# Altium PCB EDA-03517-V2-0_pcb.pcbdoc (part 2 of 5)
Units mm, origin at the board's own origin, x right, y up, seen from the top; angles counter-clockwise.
Board outline 220 x 264 mm, 8 copper layers (Top Layer, L2, L3, L4, L5, L6, L7, Bottom Layer), stack 2.18 mm thick; 439 components, 290 nets, 1011 pads, 273 vias.
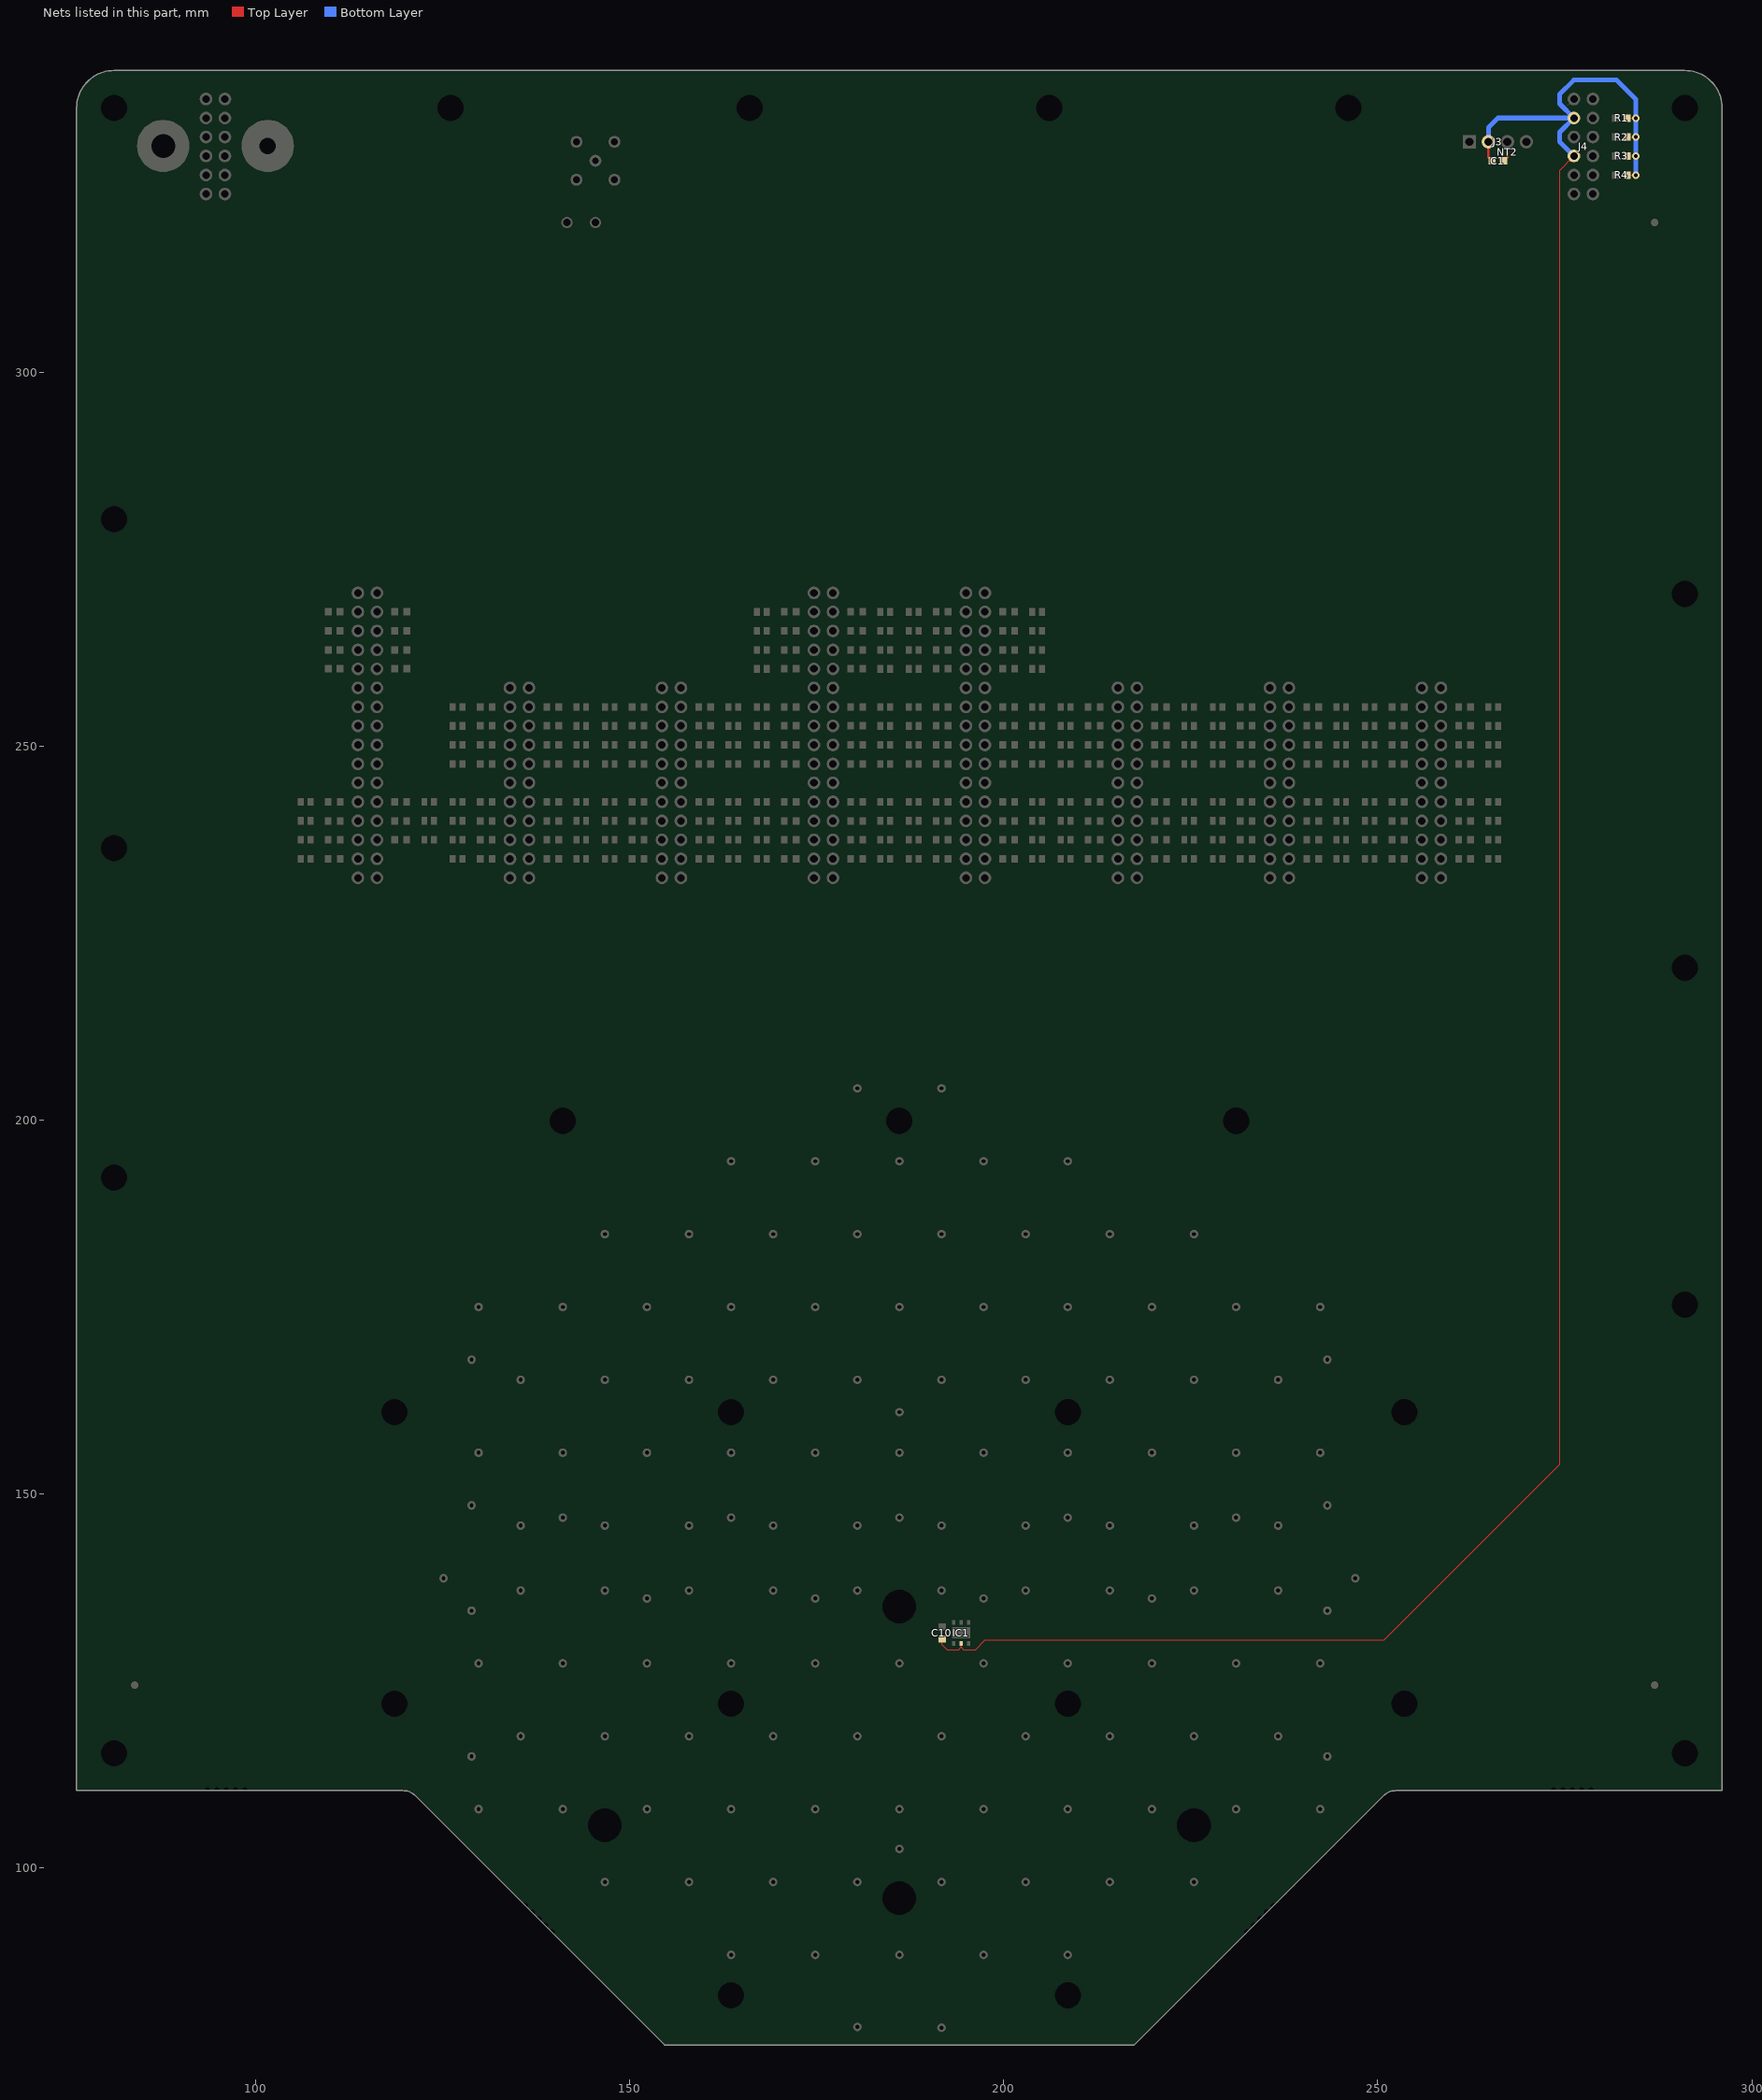
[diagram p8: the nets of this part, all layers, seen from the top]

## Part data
B1 B2: library part PLATED_HOLE1.0_PAD1.5, "Single Terminal Socket"
C1 C10: library part CC0603_100NF_50V_10%_X7R, "Non-polarised capacitor", Case=0603, Manufacturer=GENERIC, Manufacturer1 ComponentHeight=0.87mm, Manufacturer1 Example=PHYCOMP, Manufacturer1 Part Number=223858615649, Tolerance=±10%, Voltage=50V
C2: library part CC0603_1PF_50V_0.25PF_NP0, "Non-polarised capacitor", Case=0603, Manufacturer=GENERIC, Manufacturer1 ComponentHeight=0.87mm, Manufacturer1 Example=PHYCOMP, Manufacturer1 Part Number=223886715108, Tolerance=±0.25pF, Voltage=50V
C3: library part CC0603_2.2PF_50V_0.25PF_NP0, "Non-polarised capacitor", Case=0603, Manufacturer=GENERIC, Manufacturer1 ComponentHeight=0.87mm, Manufacturer1 Example=PHYCOMP, Manufacturer1 Part Number=223886715228, Tolerance=±0.25pF, Voltage=50V
C4: library part CC0603_4.7PF_50V_0.25PF_NP0, "Non-polarised capacitor", Case=0603, Manufacturer=GENERIC, Manufacturer1 ComponentHeight=0.87mm, Manufacturer1 Example=PHYCOMP, Manufacturer1 Part Number=223886715478, Tolerance=±0.25pF, Voltage=50V
C5: library part CC0603_10PF_50V_5%_NP0, "Non-polarised capacitor", Case=0603, Manufacturer=GENERIC, Manufacturer1 ComponentHeight=0.87mm, Manufacturer1 Example=PHYCOMP, Manufacturer1 Part Number=223886715109, Tolerance=±5%, Voltage=50V
C6: library part CC0603_22PF_50V_5%_NP0, "Non-polarised capacitor", Case=0603, Manufacturer=GENERIC, Manufacturer1 ComponentHeight=0.87mm, Manufacturer1 Example=PHYCOMP, Manufacturer1 Part Number=223886715229, Tolerance=±5%, Voltage=50V
C7: library part CC0603_47PF_50V_5%_NP0, "Non-polarised capacitor", Case=0603, Manufacturer=GENERIC, Manufacturer1 ComponentHeight=0.87mm, Manufacturer1 Example=PHYCOMP, Manufacturer1 Part Number=223886715479, Tolerance=±5%, Voltage=50V
C8: library part CC0603_100PF_50V_5%_NP0, "Non-polarised capacitor", Case=0603, Manufacturer=GENERIC, Manufacturer1 ComponentHeight=0.87mm, Manufacturer1 Example=PHYCOMP, Manufacturer1 Part Number=223886715101, Tolerance=±5%, Voltage=50V
C9: library part CC0603_220PF_50V_5%_NP0, "Non-polarised capacitor", Case=0603, Manufacturer=GENERIC, Manufacturer1 ComponentHeight=0.87mm, Manufacturer1 Example=PHYCOMP, Manufacturer1 Part Number=223886715221, Tolerance=±5%, Voltage=50V
FTG1 FTG2 FTG3: library part FIDUCIAL_TARGET_C100-200, "Fiducial Target"
IC1: "Humidity and Temperature Sensor IC", Case=SON6, Manufacturer=SENSIRION
J1 J4: library part SAMTEC_MTLW-106-07-L-D-250, "Connector 12 Male", Manufacturer=SAMTEC, Manufacturer Part Number=MTLW-106-07-L-D-250
J2: library part LEMO_EPK.00.250.NTN, Manufacturer=LEMO, Manufacturer Part Number=EPK.00.250.NTN
J3: library part SAMTEC_SSW-104-02-L-S-RA, "Connector 4 Female", Manufacturer=SAMTEC, Manufacturer Part Number=SSW-104-02-L-S-RA
J5 J8 J9: library part SAMTEC_MTLW-116-07-L-D-250, "Connector 32 Male", Manufacturer=SAMTEC, Manufacturer Part Number=MTLW-116-07-L-D-250
J6 J7 J10 J11 J12: library part SAMTEC_MTLW-111-07-L-D-250, "Connector 20 Male", Manufacturer=SAMTEC, Manufacturer Part Number=MTLW-111-07-L-D-250
PP1 PP2 PP3 PP4 PP5 PP6 PP7 PP8 PP9 PP10 PP11 PP12 PP13 PP14 PP15 PP16 PP17 PP18 PP19 PP20 PP21 PP22 PP23 PP24 PP25 PP26 PP27 PP28 PP29 PP30 PP31 PP32 PP33 PP34 PP35 PP36 PP37 PP38 PP39 PP40 PP41 PP42 PP43 PP44 PP45 PP46 PP47 PP48 PP49 PP50 PP51 PP52 PP53 PP54 PP55 PP56 PP57 PP58 PP59 PP60 PP61 PP62 PP63 PP64 PP65 PP66 PP67 PP68 PP69 PP70 PP71 PP72 PP73 PP74 PP75 PP76 PP77 PP78 PP79 PP80 PP81 PP82 PP83 PP84 PP85 PP86 PP87 PP88 PP89 PP90 PP91 PP92 PP93 PP94 PP95 PP96 PP97 PP98 PP99 PP100 PP101 PP102 PP103 PP104 PP105 PP106 PP107 PP108 PP109 PP110 PP111 PP112 PP113 PP114 PP115 PP116 PP117 PP118 PP119 PP120 PP121 PP122 PP123 PP124 PP125 PP126 PP127 PP128 PP129 PP130 PP131 PP132 PP133 PP134 PP135: library part MILL-MAX_0985-1-15-20-71-14-11-0, "Test Point", Manufacturer=MILL-MAX, Manufacturer Part Number=0985-1-15-20-71-14-11-0
R1 R2 R3 R4: library part R0603_10K_1%_0.1W_100PPM, "Resistor - 1%", Case=0603, Manufacturer=GENERIC, Manufacturer1 ComponentHeight=0.55mm, Manufacturer1 Example="NIC COMPONENT", Manufacturer1 Part Number=NRC06F1002TRF, Power=0.1W, Tolerance=±1%
RB1 RB2 RB3 RB4 RB5 RB6 RB7 RB8 RB9 RB10 RB11 RB12 RB13 RB14 RB15 RB16 RB17 RB18 RB19 RB20 RB21 RB22 RB23 RB24 RB25 RB26 RB27 RB28 RB29 RB30 RB31 RB32 RB33 RB34 RB35 RB36 RB37 RB38 RB39 RB40 RB41 RB42 RB43 RB44 RB45 RB46 RB47 RB48 RB49 RB50 RB51 RB52 RB53 RB54 RB55 RB56 RB57 RB58 RB59 RB60 RB61 RB62 RB63 RB64 RB65 RB66 RB67 RB68 RB69 RB70 RB71 RB72 RB73 RB74 RB75 RB76 RB77 RB78 RB79 RB80 RB81 RB82 RB83 RB84 RB85 RB86 RB87 RB88 RB89 RB90 RB91 RB92 RB93 RB94 RB95 RB96 RB97 RB98 RB99 RB100 RB101 RB102 RB103 RB104 RB105 RB106 RB107 RB108 RB109 RB110 RB111 RB112 RB113 RB114 RB115 RB116 RB117 RB118 RB119 RB120 RB121 RB122 RB123 RB124 RB125 RB126 RB127 RB128 RB129 RB130 RB131 RB132 RB133 RB134 RB135: library part R0603_10M_1%_0.125W_100PPM_VISHAY_CHP, "Resistor - 1%", Case=0603, Manufacturer="VISHAY SFERNICE", Manufacturer Part Number=CHP0603K1005FNT, Power=0.125W, Tolerance=±1%
RS1 RS2 RS3 RS4 RS5 RS6 RS7 RS8 RS9 RS10 RS11 RS12 RS13 RS14 RS15 RS16 RS17 RS18 RS19 RS20 RS21 RS22 RS23 RS24 RS25 RS26 RS27 RS28 RS29 RS30 RS31 RS32 RS33 RS34 RS35 RS36 RS37 RS38 RS39 RS40 RS41 RS42 RS43 RS44 RS45 RS46 RS47 RS48 RS49 RS50 RS51 RS52 RS53 RS54 RS55 RS56 RS57 RS58 RS59 RS60 RS61 RS62 RS63 RS64 RS65 RS66 RS67 RS68 RS69 RS70 RS71 RS72 RS73 RS74 RS75 RS76 RS77 RS78 RS79 RS80 RS81 RS82 RS83 RS84 RS85 RS86 RS87 RS88 RS89 RS90 RS91 RS92 RS93 RS94 RS95 RS96 RS97 RS98 RS99 RS100 RS101 RS102 RS103 RS104 RS105 RS106 RS107 RS108 RS109 RS110 RS111 RS112 RS113 RS114 RS115 RS116 RS117 RS118 RS119 RS120 RS121 RS122 RS123 RS124 RS125 RS126 RS127 RS128 RS129 RS130 RS131 RS132 RS133 RS134 RS135: library part R0603_0R_JUMPER, "Resistor", Case=0603, Manufacturer=GENERIC, Manufacturer1 ComponentHeight=0.55mm, Manufacturer1 Example="NIC COMPONENT", Manufacturer1 Part Number=NRC06Z0

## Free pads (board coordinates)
  round 1 hole 3.5 unplated mask+1.25: D350NP(81.055,115.36) D350NP(81.055,192.36) D350NP(81.055,236.36) D350NP(81.055,280.36) D350NP(81.055,335.36) D350NP(118.543,121.967) D350NP(118.543,160.945) D350NP(126.055,335.36) D350NP(141.047,199.923) D350NP(163.551,82.989) D350NP(163.551,121.967) D350NP(163.551,160.945) D350NP(166.055,335.36) D350NP(186.055,199.923) D350NP(206.055,335.36) D350NP(208.559,82.989) D350NP(208.559,121.967) D350NP(208.559,160.945) D350NP(231.063,199.923) D350NP(246.055,335.36) D350NP(253.567,121.967) D350NP(253.567,160.945) D350NP(291.055,115.36) D350NP(291.055,175.36) D350NP(291.055,220.36) D350NP(291.055,270.36) D350NP(291.055,335.36)
  round 7 hole 2.2: P28(101.6,330.282)
  round 7 hole 3.2: P29(87.63,330.282)
  round 0.5 hole 0.8 unplated mask+0.15: P80NP(93.555,110.36) P80NP(94.805,110.36) P80NP(96.055,110.36) P80NP(97.305,110.36) P80NP(98.555,110.36) P80NP(136.039,94.976) P80NP(136.923,94.092) P80NP(137.806,93.209) P80NP(138.69,92.325) P80NP(139.574,91.441) P80NP(232.544,91.449) P80NP(233.428,92.333) P80NP(234.312,93.217) P80NP(235.196,94.101) P80NP(236.08,94.985) P80NP(273.555,110.36) P80NP(274.805,110.36) P80NP(276.055,110.36) P80NP(277.305,110.36) P80NP(278.555,110.36)
  round 1 hole 4.5 unplated mask+1.75: P450NP(146.673,105.726) P450NP(186.055,95.982) P450NP(186.055,134.96) P450NP(225.425,105.726)

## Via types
v1: diameter 1, hole 0.5, Top Layer to Bottom Layer, tented both sides, 273 vias

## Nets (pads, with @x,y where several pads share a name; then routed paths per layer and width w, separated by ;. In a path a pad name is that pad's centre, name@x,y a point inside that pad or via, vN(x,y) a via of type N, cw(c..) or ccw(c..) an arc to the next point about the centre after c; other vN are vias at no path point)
3.3V: C1.2 C10.2 IC1.5 J3.2 J4.6 J4.10 R1.2 R2.2 R3.2 R4.2 | length 324.2
  Top Layer w0.152: C10.2@191.77,130.645 191.77,129.857 192.405,129.222 193.992,129.222 194.31,129.54 ; IC1.5@194.31,130.045 194.31,129.54 ; J4.6@276.225,328.93 274.32,327.025 274.32,153.987 250.825,130.493 197.485,130.493 196.215,129.222 194.627,129.222 194.31,129.54 ; R4.2@283.375,326.39 v1(284.48,326.39) ; R3.2@283.375,328.93 v1(284.48,328.93) ; R2.2@283.375,331.47 v1(284.48,331.47) ; R1.2@283.375,334.01 v1(284.48,334.01)
  Top Layer w0.305: J3.2@264.795,330.835 264.795,328.765 C1.2@265.265,328.295
  Bottom Layer w0.635: J3.2@264.795,330.835 264.795,332.74 266.065,334.01 J4.10@276.225,334.01 ; J4.6@276.225,328.93 274.32,330.835 274.32,332.105 J4.10@276.225,334.01 ; v1(284.48,326.39) v1(284.48,328.93) v1(284.48,331.47) v1(284.48,334.01) 284.48,336.55 281.94,339.09 276.225,339.09 274.32,337.185 274.32,335.915 J4.10@276.225,334.01
CGND: C1.1 NT2.2 | length 1.2
  Top Layer w0.305: C1.1@266.865,328.295 267.335,328.765 NT2.2@267.335,329.311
